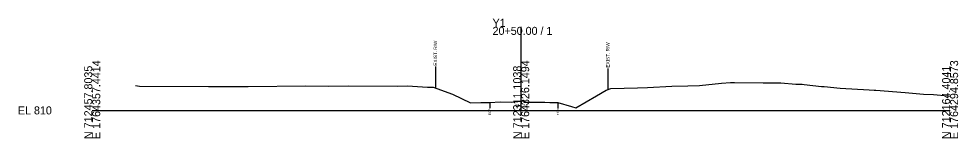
# Model space of a CAD drawing. Extents: x -26 to 1303, y -10 to 9524.
# Drawn here: x 974.3 to 1302.8, y 490.3 to 532 of the extents above; entities that cross this region are included whole.
import ezdxf

# ---------------------------------------------------------------- set-up
doc = ezdxf.new("R2010")
doc.units = 0
for name, color, linetype in [('Default', 7, 'Continuous'), ('Exist Cross Section Cell', 7, 'Continuous'), ('Exist XS Center Line Elevation Label', 7, 'Continuous'), ('Exist XS Ground Line', 7, 'Continuous'), ('Old_Level_10', 7, 'Continuous')]:
    doc.layers.add(name, color=color, linetype=linetype)

msp = doc.modelspace()

# ---------------------------------------------------------------- linework, layer by layer
at = {"layer": 'Exist Cross Section Cell'}
for p, q in [((1150, 500), (1150, 529.16)), ((1000, 500), (1150, 500)), ((1150, 500), (1300, 500))]:
    msp.add_line(p, q, dxfattribs=at)
at = {"layer": 'Exist XS Ground Line'}
msp.add_lwpolyline([(1015.09, 508.7), (1016.54, 508.46), (1040.67, 508.35), (1042.18, 508.35), (1054.52, 508.29), (1074.73, 508.53), (1082.54, 508.49), (1089.53, 508.55), (1106.68, 508.4), (1110.3, 508.57), (1117.2, 508.15), (1119.23, 508.15), (1125.95, 505.67), (1132.28, 502.68), (1135.95, 502.72), (1139.04, 502.79), (1142.64, 502.96), (1146.65, 502.91), (1150, 503.24), (1150.86, 503.32), (1150.93, 502.87), (1151.04, 502.87), (1152.41, 502.87), (1153.19, 502.88), (1154.96, 502.87), (1156.44, 502.84), (1157.52, 502.83), (1158.22, 502.82), (1160.08, 502.8), (1160.89, 502.78), (1162.19, 502.78), (1162.86, 502.73), (1167.63, 501.37), (1169.07, 500.93), (1176.34, 505.08), (1179.75, 507.02), (1181.36, 507.69), (1190.7, 507.9), (1194.17, 508.01), (1202.68, 508.47), (1208.3, 508.61), (1212.35, 508.74), (1220.07, 509.49), (1223.25, 509.72), (1224.56, 509.7), (1234.61, 509.61), (1240.86, 509.58), (1246.03, 509.11), (1248.27, 509.1), (1248.92, 509.05), (1255.06, 508.39), (1255.93, 508.31), (1261.61, 507.8), (1271.65, 507.22), (1273.44, 507.11), (1273.98, 507.08), (1284.25, 506.28), (1290.65, 505.72), (1294.16, 505.6), (1299.26, 505.04), (1300, 504.94)], dxfattribs=at)
at = {"layer": 'Old_Level_10'}
for p, q in [((1120, 515.27), (1120, 507.87)), ((1180.31, 514.65), (1180.31, 507.25)), ((1139.04, 502.79), (1139.04, 500.74)), ((1162.86, 502.73), (1162.86, 500.68))]:
    msp.add_line(p, q, dxfattribs=at)

# ---------------------------------------------------------------- texts
at = {"layer": 'Default'}
msp.add_text('-', height=0.0001, dxfattribs=at).set_placement((1000, 500))
at = {"layer": 'Exist Cross Section Cell'}
for s, p in [('Y1', (1140, 529.16)), ('20+50.00 / 1', (1140, 526.36)), ('EL 810', (974, 498.6))]:
    msp.add_text(s, height=2.8, dxfattribs=at).set_placement(p)
for s, p in [('E 1764357.4414', (1002.8, 490)), ('E 1764326.1494', (1152.8, 490)), ('E 1764294.8573', (1302.8, 490)), ('N 712457.8035', (1000, 490)), ('N 712311.1038', (1150, 490)), ('N 712164.4041', (1300, 490))]:
    msp.add_text(s, height=2.8, rotation=90, dxfattribs=at).set_placement(p)
at = {"layer": 'Exist XS Center Line Elevation Label'}
msp.add_text('813.24', height=1, dxfattribs=at).set_placement((1147.98, 501.24))
at = {"layer": 'Old_Level_10'}
for s, height, p in [('EXIST. R/W', 1.181, (1120.59, 515.57)), ('EXIST. R/W', 1.181, (1180.9, 514.95)), ('EOP', 0.787, (1139.43, 498.34)), ('EOP', 0.787, (1163.26, 498.28))]:
    msp.add_text(s, height=height, rotation=90, dxfattribs=at).set_placement(p)

doc.saveas('drawing.dxf')
